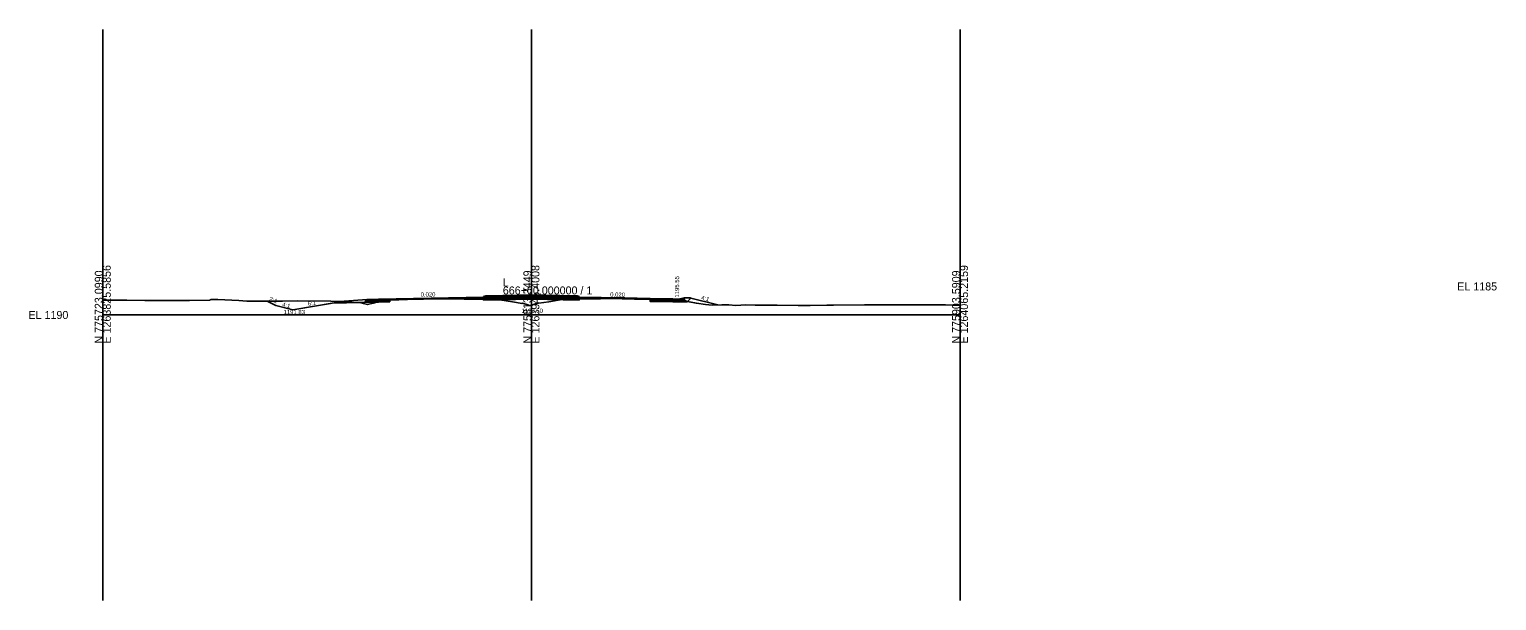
# Model space of a CAD drawing. Extents: x -41 to 1262860, y -100 to 777489.
# Drawn here: x -26 to 488, y 1595 to 1795 of the extents above; entities that cross this region are included whole.
import ezdxf

# ---------------------------------------------------------------- set-up
doc = ezdxf.new("R2010")
doc.units = 0
for name, color, linetype in [('Exist Cross Section Cell', 7, 'Continuous'), ('Exist XS Center Line Elevation Label', 7, 'Continuous'), ('Exist XS Ground Line', 7, 'Continuous'), ('Prop CMT Pvmt Course 1', 7, 'Continuous'), ('Prop CMT Pvmt Course 4', 7, 'Continuous'), ('Prop CMT Pvmt Surface', 7, 'Continuous'), ('Prop CMT Shld Paved Course 1', 7, 'Continuous'), ('Prop CMT Shld Paved Course 2', 7, 'Continuous'), ('Prop CMT Shld Paved Course 4', 7, 'Continuous'), ('Prop CMT Subgrade Earthwork', 7, 'Continuous'), ('Prop Conc Curb and Gutter', 7, 'Continuous'), ('Prop Conc Island Cover', 7, 'Continuous'), ('Prop XS Ditch Standard Text', 7, 'Continuous'), ('Prop XS Earthwork Shape', 7, 'Continuous'), ('Prop XS Elevation Labels', 7, 'Continuous'), ('Prop XS Exc Vertical Line 1', 7, 'Continuous'), ('Prop XS Exc Vertical Line 2', 7, 'Continuous'), ('Prop XS Exc Vertical Line 3', 7, 'Continuous'), ('Prop XS Finish Grade', 7, 'Continuous'), ('Prop XS Finish Grade Earthwork', 7, 'Continuous'), ('Prop XS SE Text', 7, 'Continuous'), ('Prop XS Side Slope Text', 7, 'Continuous'), ('Scratch_Level_4', 7, 'Continuous'), ('Scratch_Level_6', 7, 'Continuous'), ('Typical Curb CELL', 7, 'Continuous')]:
    doc.layers.add(name, color=color, linetype=linetype)

msp = doc.modelspace()

# ---------------------------------------------------------------- linework, layer by layer
at = {"layer": 'Exist Cross Section Cell'}
for p, q in [((150, 1695), (150, 1705)), ((0, 1695), (150, 1695)), ((150, 1695), (300, 1695))]:
    msp.add_line(p, q, dxfattribs=at)
at = {"layer": 'Exist XS Ground Line'}
msp.add_lwpolyline([(0, 1700.23), (1.65, 1700.22), (8.44, 1700.23), (14.72, 1700.08), (18.6, 1700.02), (26.21, 1700.04), (30.34, 1700.11), (37.42, 1700.25), (37.54, 1700.31), (37.92, 1700.48), (40.28, 1700.39), (47.63, 1700.07), (50.39, 1699.84), (58.3, 1699.85), (62.9, 1699.84), (68.05, 1699.91), (79.78, 1699.84), (82.59, 1699.76), (84.19, 1699.64), (90.03, 1699.34), (91.22, 1699.06), (92.6, 1698.67), (94.62, 1699.13), (96.73, 1699.68), (98.5, 1700.2), (99.73, 1700.24), (100.19, 1700.24), (109.79, 1700.49), (110.59, 1700.51), (112.27, 1700.53), (122.45, 1700.65), (134.32, 1700.41), (135.32, 1700.39), (135.47, 1700.38), (138.8, 1700.28), (140.47, 1700.02), (144.82, 1699.35), (146.62, 1699.07), (146.89, 1699.14), (148.77, 1698.58), (149, 1698.48), (149.46, 1698.36), (149.92, 1698.47), (152.55, 1699.22), (152.65, 1699.09), (156.11, 1699.64), (159.38, 1700.25), (160.82, 1700.4), (163.7, 1700.55), (164.53, 1700.59), (174.14, 1700.69), (176.62, 1700.72), (186.75, 1700.59), (189.13, 1700.56), (192, 1700.43), (200.95, 1700.08), (202.5, 1699.96), (202.88, 1699.92), (203.81, 1699.76), (204.52, 1699.73), (207.74, 1699.1), (210.91, 1698.71), (213.31, 1698.42), (216.61, 1698.6), (219.09, 1698.53), (221.54, 1698.37), (225.06, 1698.53), (228.28, 1698.42), (235.98, 1698.4), (243.38, 1698.36), (247.4, 1698.29), (247.53, 1698.29), (253.33, 1698.39), (255.77, 1698.4), (266.53, 1698.55), (274.01, 1698.53), (275.47, 1698.58), (278.36, 1698.54), (286.56, 1698.57), (289.98, 1698.58), (294.89, 1698.53), (297.37, 1698.47), (300, 1698.48)], dxfattribs=at)
at = {"layer": 'Prop CMT Pvmt Course 1'}
for q in [(133.25, 1701.28), (166.75, 1701.28)]:
    msp.add_line((150, 1701.62), q, dxfattribs=at)
for points in [[(96.53, 1700.3), (96.53, 1700.55), (133.25, 1701.28), (133.25, 1701.28), (133.25, 1701.03), (133.25, 1701.03), (133.25, 1701.03), (96.53, 1700.3), (96.53, 1700.3)], [(191.52, 1700.54), (191.52, 1700.79), (187.06, 1700.88), (187.06, 1700.88), (186.7, 1700.89), (186.7, 1700.89), (186.08, 1700.9), (186.08, 1700.9), (185.27, 1700.91), (185.27, 1700.91), (184.38, 1700.93), (184.38, 1700.93), (183.5, 1700.95), (183.5, 1700.95), (182.75, 1700.97), (182.75, 1700.97), (182.22, 1700.98), (182.22, 1700.98), (166.75, 1701.28), (166.75, 1701.28), (166.75, 1701.03), (166.75, 1701.03), (166.75, 1701.03), (182.22, 1700.73), (182.22, 1700.73), (182.75, 1700.72), (182.75, 1700.72), (183.5, 1700.7), (183.5, 1700.7), (184.38, 1700.68), (184.38, 1700.68), (185.27, 1700.66), (185.27, 1700.66), (186.08, 1700.65), (186.08, 1700.65), (186.7, 1700.64), (186.7, 1700.64), (187.06, 1700.63), (187.06, 1700.63), (191.52, 1700.54), (191.52, 1700.54)]]:
    msp.add_lwpolyline(points, dxfattribs=at)
at = {"layer": 'Prop CMT Pvmt Course 4'}
for p, q in [((191.52, 1700.21), (199.52, 1700.05)), ((191.52, 1699.75), (191.52, 1700.21)), ((191.52, 1699.75), (199.52, 1699.59)), ((199.52, 1700.05), (204.02, 1700.05)), ((204.02, 1700.05), (204.48, 1699.59)), ((199.52, 1699.59), (204.48, 1699.59))]:
    msp.add_line(p, q, dxfattribs=at)
at = {"layer": 'Prop CMT Pvmt Surface'}
for p, q in [((92.5, 1700.47), (96.53, 1700.55)), ((96.53, 1700.55), (133.25, 1701.28)), ((133.25, 1701.28), (150, 1701.62)), ((150, 1701.62), (166.75, 1701.28)), ((166.75, 1701.28), (191.52, 1700.79)), ((191.52, 1700.79), (199.52, 1700.63))]:
    msp.add_line(p, q, dxfattribs=at)
at = {"layer": 'Prop CMT Shld Paved Course 1'}
msp.add_line((199.77, 1700.37), (199.77, 1700.37), dxfattribs=at)
msp.add_line((199.77, 1700.37), (199.77, 1700.37), dxfattribs=at)
for points in [[(96.53, 1700.55), (96.53, 1700.55), (96.53, 1700.3), (96.53, 1700.3), (96.53, 1700.3), (92.24, 1700.21), (92.5, 1700.47), (92.5, 1700.47), (96.53, 1700.55)], [(199.52, 1700.63), (191.52, 1700.79), (191.52, 1700.54), (191.52, 1700.54), (195.75, 1700.46), (195.75, 1700.46), (199.52, 1700.38), (199.52, 1700.63), (195.5, 1700.71)]]:
    msp.add_lwpolyline(points, dxfattribs=at)
at = {"layer": 'Prop CMT Shld Paved Course 2'}
for p, q in [((96.53, 1699.97), (96.53, 1700.3)), ((96.53, 1700.3), (96.73, 1700.3)), ((96.73, 1699.97), (96.53, 1699.97)), ((96.53, 1699.97), (96.53, 1699.97)), ((96.73, 1700.3), (98.5, 1700.34)), ((96.73, 1700.3), (96.73, 1700.3)), ((100.5, 1700.05), (96.73, 1699.97)), ((96.73, 1699.97), (96.73, 1699.97)), ((97.78, 1699.99), (97.78, 1699.99)), ((98.5, 1700.34), (99.73, 1700.36)), ((98.5, 1700.34), (98.5, 1700.34)), ((98.5, 1700.2), (98.5, 1700.2)), ((99.73, 1700.36), (100.19, 1700.37)), ((99.73, 1700.36), (99.73, 1700.36)), ((99.73, 1700.24), (99.73, 1700.24)), ((100.19, 1700.37), (109.79, 1700.57)), ((100.19, 1700.37), (100.19, 1700.37)), ((100.19, 1700.24), (100.19, 1700.24)), ((109.79, 1700.49), (100.5, 1700.25)), ((109.79, 1700.57), (110.59, 1700.58)), ((109.79, 1700.57), (109.79, 1700.57)), ((110.59, 1700.51), (109.79, 1700.49)), ((109.79, 1700.49), (109.79, 1700.49)), ((110.59, 1700.58), (112.27, 1700.62)), ((112.27, 1700.53), (110.59, 1700.51)), ((112.27, 1700.62), (122.45, 1700.82)), ((122.45, 1700.65), (112.27, 1700.53)), ((112.27, 1700.62), (112.27, 1700.62)), ((112.27, 1700.53), (112.27, 1700.53)), ((122.45, 1700.82), (133.25, 1701.03)), ((122.45, 1700.82), (122.45, 1700.82)), ((126.48, 1700.57), (122.45, 1700.65)), ((122.45, 1700.65), (122.45, 1700.65)), ((133.25, 1700.7), (126.48, 1700.57)), ((126.48, 1700.57), (126.48, 1700.57)), ((150, 1701.37), (133.25, 1701.03)), ((150, 1701.04), (133.25, 1700.7)), ((133.25, 1701.03), (133.25, 1701.03)), ((133.25, 1701.03), (133.25, 1700.7)), ((133.25, 1700.7), (133.25, 1700.7)), ((133.25, 1700.7), (133.25, 1700.7)), ((166.75, 1701.03), (150, 1701.37)), ((150, 1701.04), (166.75, 1700.7)), ((174.14, 1700.89), (166.75, 1701.03)), ((166.75, 1701.03), (166.75, 1700.7)), ((166.75, 1700.7), (166.75, 1700.7)), ((166.75, 1700.7), (166.75, 1700.7)), ((166.75, 1700.7), (169.64, 1700.64)), ((169.64, 1700.64), (174.14, 1700.69)), ((176.62, 1700.84), (174.14, 1700.89)), ((174.14, 1700.89), (174.14, 1700.89)), ((174.14, 1700.69), (176.62, 1700.72)), ((174.14, 1700.69), (174.14, 1700.69)), ((182.22, 1700.73), (176.62, 1700.84)), ((176.62, 1700.84), (176.62, 1700.84)), ((176.62, 1700.84), (176.62, 1700.84)), ((176.62, 1700.72), (176.62, 1700.72)), ((176.62, 1700.72), (176.62, 1700.72)), ((176.62, 1700.72), (182.22, 1700.65)), ((182.75, 1700.72), (182.22, 1700.73)), ((182.22, 1700.73), (182.22, 1700.73)), ((182.22, 1700.65), (182.22, 1700.65)), ((182.22, 1700.65), (182.75, 1700.64)), ((183.5, 1700.7), (182.75, 1700.72)), ((182.75, 1700.72), (182.75, 1700.72)), ((182.75, 1700.64), (182.75, 1700.64)), ((182.75, 1700.64), (183.5, 1700.63)), ((184.38, 1700.68), (183.5, 1700.7)), ((183.5, 1700.7), (183.5, 1700.7)), ((183.5, 1700.63), (183.5, 1700.63)), ((183.5, 1700.63), (184.38, 1700.62)), ((185.27, 1700.66), (184.38, 1700.68)), ((184.38, 1700.68), (184.38, 1700.68)), ((184.38, 1700.62), (184.38, 1700.62)), ((184.38, 1700.62), (185.27, 1700.61)), ((186.08, 1700.65), (185.27, 1700.66)), ((185.27, 1700.66), (185.27, 1700.66)), ((185.27, 1700.61), (185.27, 1700.61)), ((185.27, 1700.61), (186.08, 1700.6)), ((186.7, 1700.64), (186.08, 1700.65)), ((186.08, 1700.65), (186.08, 1700.65)), ((186.08, 1700.6), (186.08, 1700.6)), ((186.08, 1700.6), (186.7, 1700.59)), ((186.75, 1700.64), (186.7, 1700.64)), ((186.7, 1700.59), (186.75, 1700.59)), ((187.06, 1700.63), (186.75, 1700.64)), ((186.75, 1700.64), (186.75, 1700.64)), ((186.75, 1700.59), (186.75, 1700.59)), ((186.75, 1700.59), (187.06, 1700.59)), ((189.13, 1700.59), (187.06, 1700.63)), ((187.06, 1700.59), (189.13, 1700.56)), ((191.52, 1700.54), (189.13, 1700.59)), ((189.13, 1700.59), (189.13, 1700.59)), ((189.13, 1700.59), (189.13, 1700.59)), ((189.13, 1700.59), (189.13, 1700.59)), ((189.13, 1700.56), (189.13, 1700.56)), ((189.13, 1700.56), (189.13, 1700.56)), ((189.13, 1700.56), (189.13, 1700.56)), ((189.13, 1700.56), (191.52, 1700.45)), ((191.52, 1700.45), (191.52, 1700.54)), ((191.52, 1700.54), (191.52, 1700.54)), ((191.52, 1700.45), (191.52, 1700.45)), ((191.52, 1700.45), (191.52, 1700.45)), ((199.77, 1700.37), (199.77, 1700.37))]:
    msp.add_line(p, q, dxfattribs=at)
for points in [[(96.53, 1700.3), (96.53, 1700.3), (96.53, 1699.97), (96.53, 1699.97), (96.53, 1699.97), (91.9, 1699.87), (92.24, 1700.21), (92.24, 1700.21), (96.5, 1700.3)], [(195.75, 1700.46), (191.52, 1700.54), (191.52, 1700.21), (191.52, 1700.21), (196.09, 1700.12), (196.09, 1700.12), (199.52, 1700.05), (199.52, 1700.38), (195.75, 1700.46)]]:
    msp.add_lwpolyline(points, dxfattribs=at)
at = {"layer": 'Prop CMT Shld Paved Course 4'}
for p, q in [((96.73, 1699.68), (96.53, 1699.63)), ((97.78, 1699.99), (96.73, 1699.68)), ((133.25, 1700.43), (126.48, 1700.57)), ((133.25, 1700.24), (133.25, 1700.7)), ((133.25, 1700.24), (150, 1700.58)), ((134.25, 1700.26), (133.25, 1700.24)), ((150, 1700.58), (166.75, 1700.24)), ((166.75, 1700.24), (166.75, 1700.7)), ((166.75, 1700.61), (169.64, 1700.64))]:
    msp.add_line(p, q, dxfattribs=at)
msp.add_lwpolyline([(96.53, 1699.97), (96.53, 1699.97), (96.53, 1699.51), (96.53, 1699.51), (96.53, 1699.51), (91.44, 1699.41), (91.9, 1699.87), (91.9, 1699.87), (91.9, 1699.87), (91.9, 1699.87), (96.5, 1699.97)], dxfattribs=at)
at = {"layer": 'Prop CMT Subgrade Earthwork'}
for p, q in [((100.5, 1699.6), (100.5, 1700.25)), ((133.25, 1700.24), (150, 1700.58)), ((133.25, 1700.24), (133.25, 1700.43)), ((166.75, 1700.24), (150, 1700.58)), ((166.75, 1700.24), (166.75, 1700.61)), ((191.52, 1699.75), (191.52, 1700.45)), ((191.52, 1699.75), (199.52, 1699.59)), ((204.48, 1699.59), (205.79, 1700.9)), ((100.5, 1699.6), (80.33, 1699.13)), ((199.52, 1699.59), (204.48, 1699.59))]:
    msp.add_line(p, q, dxfattribs=at)
at = {"layer": 'Prop Conc Curb and Gutter'}
for p, q in [((133.25, 1701.28), (133.26, 1701.45)), ((133.25, 1701.28), (133.25, 1701.28)), ((133.25, 1701.28), (133.25, 1701.28)), ((133.25, 1701.28), (133.25, 1701.16)), ((135.01, 1701.28), (133.25, 1701.28)), ((133.25, 1701.16), (133.25, 1701.16)), ((133.25, 1701.16), (135.01, 1701.16)), ((133.26, 1701.45), (134.01, 1701.7)), ((133.26, 1701.45), (133.26, 1701.45)), ((134.01, 1701.7), (135.01, 1701.72)), ((134.01, 1701.7), (134.01, 1701.7)), ((135.01, 1701.72), (135.01, 1701.28)), ((135.01, 1701.28), (135.01, 1701.28)), ((135.01, 1701.16), (135.01, 1701.28)), ((135.01, 1701.16), (135.01, 1701.16)), ((135.01, 1701.16), (135.01, 1701.16)), ((165.99, 1701.7), (164.99, 1701.72)), ((164.99, 1701.72), (164.99, 1701.28)), ((166.75, 1701.28), (164.99, 1701.28)), ((164.99, 1701.28), (164.99, 1701.16)), ((164.99, 1701.28), (164.99, 1701.28)), ((164.99, 1701.16), (164.99, 1701.16)), ((164.99, 1701.16), (166.75, 1701.16)), ((166.74, 1701.45), (165.99, 1701.7)), ((165.99, 1701.7), (165.99, 1701.7)), ((166.75, 1701.28), (166.74, 1701.45)), ((166.74, 1701.45), (166.74, 1701.45)), ((166.75, 1701.16), (166.75, 1701.28)), ((166.75, 1701.28), (166.75, 1701.28)), ((166.75, 1701.28), (166.75, 1701.28)), ((166.75, 1701.16), (166.75, 1701.16)), ((166.75, 1701.16), (166.75, 1701.16))]:
    msp.add_line(p, q, dxfattribs=at)
at = {"layer": 'Prop Conc Island Cover'}
for p, q in [((135.01, 1701.72), (150, 1702.02)), ((135.01, 1701.47), (150, 1701.77)), ((135.01, 1701.72), (135.01, 1701.47)), ((164.99, 1701.72), (150, 1702.02)), ((164.99, 1701.47), (150, 1701.77)), ((164.99, 1701.47), (164.99, 1701.72)), ((164.99, 1701.72), (164.99, 1701.72)), ((164.99, 1701.47), (164.99, 1701.47))]:
    msp.add_line(p, q, dxfattribs=at)
at = {"layer": 'Prop XS Earthwork Shape'}
for points in [[(82.59, 1699.76), (83.64, 1699.68), (80.33, 1699.13), (66.53, 1696.83), (60.53, 1698.33), (57.51, 1699.85), (58.3, 1699.85), (62.9, 1699.84), (68.05, 1699.91), (79.78, 1699.84)], [(83.64, 1699.68), (84.19, 1699.64), (89.75, 1699.35), (80.33, 1699.13)], [(133.25, 1700.43), (134.32, 1700.41), (135.32, 1700.39), (135.47, 1700.38), (137.31, 1700.32), (133.25, 1700.24)], [(137.31, 1700.32), (150, 1700.58), (160.51, 1700.37), (159.38, 1700.25), (156.11, 1699.64), (152.65, 1699.09), (152.55, 1699.22), (149.92, 1698.47), (149.46, 1698.36), (149, 1698.48), (148.77, 1698.58), (146.89, 1699.14), (146.62, 1699.07), (144.82, 1699.35), (140.47, 1700.02), (138.8, 1700.28)], [(166.75, 1700.24), (166.75, 1700.61), (164.53, 1700.59), (163.7, 1700.55), (160.82, 1700.4), (160.51, 1700.37)], [(191.52, 1700.45), (192, 1700.43), (200.95, 1700.08), (202.5, 1699.96), (202.88, 1699.92), (203.81, 1699.76), (204.52, 1699.73), (204.61, 1699.72), (204.48, 1699.59), (199.52, 1699.59), (191.52, 1699.75)], [(205.79, 1700.9), (215.29, 1698.52), (213.31, 1698.42), (210.91, 1698.71), (207.74, 1699.1), (204.61, 1699.72)], [(91.42, 1699.39), (89.75, 1699.35), (90.03, 1699.34), (91.22, 1699.06), (92.6, 1698.67), (94.62, 1699.13), (96.02, 1699.5)], [(96.53, 1699.51), (96.02, 1699.5), (96.53, 1699.63)]]:
    msp.add_lwpolyline(points, close=True, dxfattribs=at)
at = {"layer": 'Prop XS Exc Vertical Line 1'}
msp.add_line((0, 1595), (0, 1795), dxfattribs=at)
at = {"layer": 'Prop XS Exc Vertical Line 2'}
msp.add_line((150, 1595), (150, 1795), dxfattribs=at)
at = {"layer": 'Prop XS Exc Vertical Line 3'}
msp.add_line((300, 1595), (300, 1795), dxfattribs=at)
at = {"layer": 'Prop XS Finish Grade'}
for p, q in [((57.51, 1699.85), (60.53, 1698.33)), ((84.53, 1699.83), (66.53, 1696.83)), ((92.5, 1700.47), (91.42, 1699.39)), ((166.75, 1701.28), (166.75, 1701.28)), ((205.79, 1700.9), (215.29, 1698.52)), ((66.53, 1696.83), (60.53, 1698.33))]:
    msp.add_line(p, q, dxfattribs=at)
msp.add_lwpolyline([(84.53, 1699.83), (92.5, 1700.47), (92.5, 1700.47)], dxfattribs=at)
at = {"layer": 'Prop XS Finish Grade Earthwork'}
for p, q in [((203.52, 1701.05), (205.52, 1700.97)), ((205.52, 1700.97), (205.79, 1700.9))]:
    msp.add_line(p, q, dxfattribs=at)
at = {"layer": 'Scratch_Level_4'}
msp.add_line((300, 1595), (300, 1795), dxfattribs=at)
at = {"layer": 'Scratch_Level_6'}
msp.add_line((0, 1795), (0, 1595), dxfattribs=at)
at = {"layer": 'Typical Curb CELL'}
for p, q in [((199.52, 1700.05), (199.52, 1700.63)), ((199.52, 1700.63), (201.52, 1700.55)), ((203.52, 1700.05), (199.52, 1700.05)), ((199.69, 1700.4), (199.77, 1700.52)), ((199.81, 1700.4), (199.69, 1700.4)), ((199.77, 1700.52), (199.81, 1700.4)), ((200.05, 1700.16), (200.11, 1700.27)), ((200.21, 1700.2), (200.05, 1700.16)), ((200.11, 1700.27), (200.21, 1700.2)), ((200.73, 1700.35), (200.82, 1700.47)), ((200.85, 1700.36), (200.73, 1700.35)), ((200.82, 1700.47), (200.85, 1700.36)), ((201.5, 1700.3), (201.56, 1700.42)), ((201.66, 1700.34), (201.5, 1700.3)), ((201.52, 1700.55), (203.52, 1701.05)), ((201.56, 1700.42), (201.66, 1700.34)), ((201.98, 1700.35), (202.07, 1700.47)), ((202.1, 1700.36), (201.98, 1700.35)), ((202.07, 1700.47), (202.1, 1700.36)), ((202.75, 1700.3), (202.81, 1700.42)), ((202.91, 1700.34), (202.75, 1700.3)), ((202.81, 1700.42), (202.91, 1700.34)), ((203.33, 1700.55), (203.34, 1700.46)), ((203.48, 1700.5), (203.33, 1700.55)), ((203.34, 1700.46), (203.48, 1700.5)), ((203.52, 1700.05), (203.52, 1701.05))]:
    msp.add_line(p, q, dxfattribs=at)
for centre in [(199.62, 1700.53), (199.66, 1700.29), (199.77, 1700.13), (199.95, 1700.27), (200.02, 1700.5), (200.23, 1700.49), (200.38, 1700.21), (200.59, 1700.44), (200.62, 1700.57), (200.88, 1700.14), (200.99, 1700.49), (201.05, 1700.31), (201.11, 1700.28), (201.14, 1700.41), (201.19, 1700.13), (201.22, 1700.4), (201.27, 1700.44), (201.31, 1700.32), (201.43, 1700.16), (201.51, 1700.36), (201.54, 1700.24), (201.71, 1700.34), (201.73, 1700.39), (201.74, 1700.45), (201.8, 1700.31), (201.89, 1700.36), (201.89, 1700.15), (201.95, 1700.51), (201.99, 1700.36), (202.11, 1700.31), (202.25, 1700.18), (202.3, 1700.31), (202.36, 1700.28), (202.39, 1700.41), (202.41, 1700.6), (202.51, 1700.44), (202.56, 1700.32), (202.57, 1700.14), (202.76, 1700.36), (202.76, 1700.66), (202.78, 1700.26), (202.96, 1700.34), (202.98, 1700.39), (203.14, 1700.73), (203.23, 1700.36), (203.26, 1700.21), (203.34, 1700.76), (203.35, 1700.31), (203.45, 1700.59)]:
    msp.add_circle(centre, 0.00802, dxfattribs=at)

# ---------------------------------------------------------------- texts
at = {"layer": 'Exist Cross Section Cell'}
for s, p in [('N 775723.0990', (0, 1685)), ('E 1263825.5856', (2.8, 1685)), ('N 775813.3449', (150, 1685)), ('E 1263945.4008', (152.8, 1685)), ('N 775903.5909', (300, 1685)), ('E 1264065.2159', (302.8, 1685))]:
    msp.add_text(s, height=2.8, rotation=90, dxfattribs=at).set_placement(p)
for s, p in [('666+00.000000 / 1', (140, 1702.2)), ('L', (140, 1705)), ('EL 1185', (474, 1703.6)), ('EL 1190', (-26, 1693.6))]:
    msp.add_text(s, height=2.8, dxfattribs=at).set_placement(p)
at = {"layer": 'Exist XS Center Line Elevation Label'}
msp.add_text('1193.50', height=1.5, dxfattribs=at).set_placement((146.55, 1695.75))
at = {"layer": 'Prop XS Ditch Standard Text'}
msp.add_text('1191.83', height=1.5, dxfattribs=at).set_placement((63.27, 1695.29))
at = {"layer": 'Prop XS Elevation Labels'}
msp.add_text('1195.55', height=1.5, rotation=90, dxfattribs=at).set_placement((201.71, 1701.12))
at = {"layer": 'Prop XS SE Text'}
for rotation, p in [(1.1458, (111.25, 1701.39)), (358.8542, (177.56, 1701.43))]:
    msp.add_text('0.020', height=1.5, rotation=rotation, dxfattribs=at).set_placement(p)
at = {"layer": 'Prop XS Side Slope Text'}
for s, rotation, p in [('2:1', 339.7612, (58.06, 1700.06)), ('6:1', 9.4623, (71.85, 1698.17)), ('4:1', 345.9638, (209.3, 1700.41)), ('4:1', 345.9638, (62.65, 1698.02))]:
    msp.add_text(s, height=1.5, rotation=rotation, dxfattribs=at).set_placement(p)

doc.saveas('drawing.dxf')
